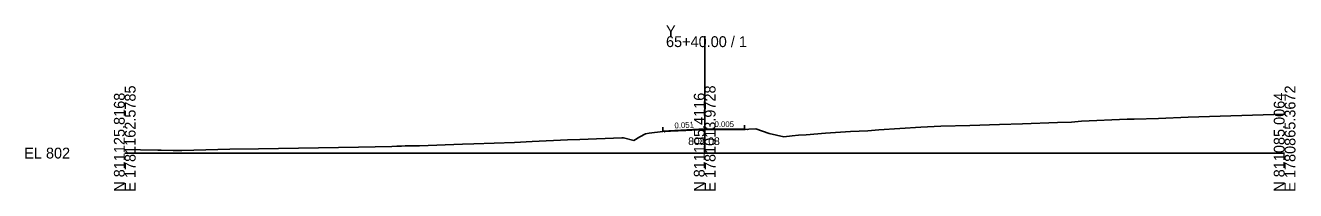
# Model space of a CAD drawing. Extents: x -12583 to 5303, y -44 to 25667.
# Drawn here: x 4974.3 to 5302.8, y 5990.3 to 6033 of the extents above; entities that cross this region are included whole.
import ezdxf

# ---------------------------------------------------------------- set-up
doc = ezdxf.new("R2010")
doc.units = 0
for name, color, linetype in [('Exist Cross Section Cell', 7, 'Continuous'), ('Exist XS Center Line Elevation Label', 7, 'Continuous'), ('Exist XS Ground Line', 7, 'Continuous'), ('Prop XS Dump Level', 7, 'Continuous'), ('Prop XS EOT Tick Mark', 7, 'Continuous'), ('Prop XS Finish Grade Pavement', 7, 'Continuous'), ('Prop XS SE Text', 7, 'Continuous')]:
    doc.layers.add(name, color=color, linetype=linetype)

msp = doc.modelspace()

# ---------------------------------------------------------------- linework, layer by layer
at = {"layer": 'Exist Cross Section Cell'}
for p, q in [((5150, 6000), (5150, 6030.2)), ((5000, 6000), (5150, 6000)), ((5150, 6000), (5300, 6000))]:
    msp.add_line(p, q, dxfattribs=at)
at = {"layer": 'Exist XS Ground Line'}
for p, q in [((5261.12, 6008.79), (5267.41, 6008.98)), ((5267.41, 6008.98), (5275.04, 6009.32)), ((5275.04, 6009.32), (5300, 6010.07)), ((5135.62, 6005.14), (5139.15, 6005.58)), ((5139.15, 6005.58), (5145.14, 6005.85)), ((5145.14, 6005.85), (5149.71, 6006.08)), ((5149.71, 6006.08), (5151.71, 6006.11)), ((5151.71, 6006.11), (5160.3, 6006.07)), ((5160.3, 6006.07), (5161.38, 6006.2)), ((5161.38, 6006.2), (5163.2, 6006.31)), ((5163.2, 6006.31), (5166.69, 6005.1)), ((5181.27, 6005.12), (5187.71, 6005.59)), ((5187.71, 6005.59), (5192.24, 6005.73)), ((5192.24, 6005.73), (5195.01, 6006.03)), ((5195.01, 6006.03), (5205.89, 6006.73)), ((5205.89, 6006.73), (5211.05, 6006.96)), ((5211.05, 6006.96), (5218.61, 6007.14)), ((5218.61, 6007.14), (5226.25, 6007.35)), ((5226.25, 6007.35), (5232.22, 6007.59)), ((5232.22, 6007.59), (5241.26, 6007.89)), ((5241.26, 6007.89), (5244.85, 6008.03)), ((5244.85, 6008.03), (5247.46, 6008.23)), ((5247.46, 6008.23), (5259.26, 6008.78)), ((5259.26, 6008.78), (5261.12, 6008.79)), ((5087.39, 6002.27), (5090.29, 6002.37)), ((5090.29, 6002.37), (5100.85, 6002.76)), ((5100.85, 6002.76), (5105.4, 6002.99)), ((5105.4, 6002.99), (5114.55, 6003.43)), ((5114.55, 6003.43), (5117.73, 6003.52)), ((5117.73, 6003.52), (5128.56, 6003.93)), ((5128.56, 6003.93), (5129.02, 6003.95)), ((5129.02, 6003.95), (5131.64, 6003.25)), ((5131.64, 6003.25), (5133.22, 6004.2)), ((5133.22, 6004.2), (5134.73, 6004.95)), ((5134.73, 6004.95), (5135.62, 6005.14)), ((5166.69, 6005.1), (5170.5, 6004.19)), ((5170.5, 6004.19), (5172.63, 6004.43)), ((5172.63, 6004.43), (5174.27, 6004.61)), ((5174.27, 6004.61), (5176.28, 6004.7)), ((5176.28, 6004.7), (5181.27, 6005.12)), ((5000, 6000.92), (5004.11, 6000.82)), ((5004.11, 6000.82), (5008.59, 6000.72)), ((5008.59, 6000.72), (5009.44, 6000.73)), ((5009.44, 6000.73), (5012.52, 6000.66)), ((5012.52, 6000.66), (5013.55, 6000.65)), ((5013.55, 6000.65), (5014.76, 6000.68)), ((5014.76, 6000.68), (5027.18, 6000.99)), ((5027.18, 6000.99), (5034.56, 6001.1)), ((5034.56, 6001.1), (5060.42, 6001.49)), ((5060.42, 6001.49), (5069.05, 6001.72)), ((5069.05, 6001.72), (5070.41, 6001.75)), ((5070.41, 6001.75), (5071.6, 6001.75)), ((5071.6, 6001.75), (5072.57, 6001.84)), ((5072.57, 6001.84), (5076.24, 6001.9)), ((5076.24, 6001.9), (5087.39, 6002.27))]:
    msp.add_line(p, q, dxfattribs=at)
at = {"layer": 'Prop XS Dump Level'}
for p, q in [((5139.15, 6005.7), (5150, 6006.26)), ((5150, 6006.26), (5160.3, 6006.21))]:
    msp.add_line(p, q, dxfattribs=at)
at = {"layer": 'Prop XS EOT Tick Mark'}
for p, q in [((5139.15, 6005.7), (5139.15, 6006.7)), ((5160.3, 6006.21), (5160.3, 6007.21))]:
    msp.add_line(p, q, dxfattribs=at)
at = {"layer": 'Prop XS Finish Grade Pavement'}
for p, q in [((5139.15, 6005.7), (5150, 6006.26)), ((5150, 6006.26), (5160.3, 6006.21))]:
    msp.add_line(p, q, dxfattribs=at)

# ---------------------------------------------------------------- texts
at = {"layer": 'Exist Cross Section Cell'}
for s, p in [('Y', (5140, 6030.2)), ('65+40.00 / 1', (5140, 6027.4)), ('EL 802', (4974, 5998.6))]:
    msp.add_text(s, height=2.8, dxfattribs=at).set_placement(p)
for s, p in [('N 811125.8168', (5000, 5990)), ('E 1781162.5785', (5002.8, 5990)), ('N 811105.4116', (5150, 5990)), ('E 1781013.9728', (5152.8, 5990)), ('N 811085.0064', (5300, 5990)), ('E 1780865.3672', (5302.8, 5990))]:
    msp.add_text(s, height=2.8, rotation=90, dxfattribs=at).set_placement(p)
at = {"layer": 'Exist XS Center Line Elevation Label'}
msp.add_text('808.08', height=2, dxfattribs=at).set_placement((5145.73, 6002.08))
at = {"layer": 'Prop XS Dump Level'}
for p in [(5139.15, 6005.28), (5160.3, 6005.77)]:
    msp.add_text('Eop', height=0.3, dxfattribs=at).set_placement(p)
at = {"layer": 'Prop XS SE Text'}
for s, rotation, p in [('0.051', 2.9081, (5142.23, 6006.36)), ('0.005', 359.7193, (5152.55, 6006.74))]:
    msp.add_text(s, height=1.5, rotation=rotation, dxfattribs=at).set_placement(p)

doc.saveas('drawing.dxf')
